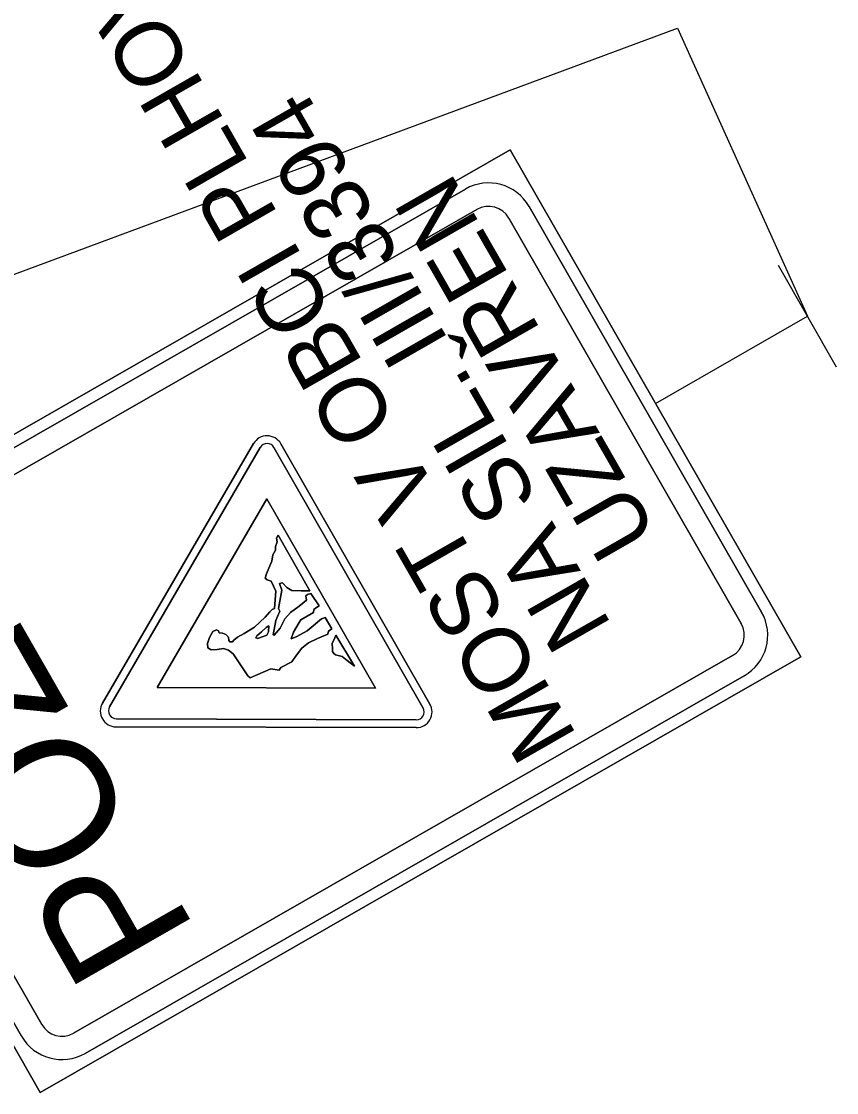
# Model space of a CAD drawing. Extents: x -688893 to -679983, y -1088371 to -1075771.
# Drawn here: x -682889 to -682470, y -1076904 to -1076354 of the extents above; entities that cross this region are included whole.
import ezdxf

# ---------------------------------------------------------------- set-up
doc = ezdxf.new("R2010")
doc.units = 0
for name, color, linetype in [('SDZ', 7, 'Continuous'), ('SDZ plochy', 7, 'Continuous'), ('SDZ symbol', 7, 'Continuous')]:
    doc.layers.add(name, color=color, linetype=linetype)

msp = doc.modelspace()

# ---------------------------------------------------------------- linework, layer by layer
at = {"layer": 'SDZ'}
for p, q in [((-683028.12, -1076644.18), (-682637.66, -1076420.48)), ((-682637.66, -1076420.48), (-682488.53, -1076680.79)), ((-682999.11, -1076634.47), (-682660.71, -1076440.6)), ((-682993.14, -1076644.89), (-682654.75, -1076451.01)), ((-682627.96, -1076449.49), (-682508.65, -1076657.74)), ((-682638.37, -1076455.46), (-682519.06, -1076663.7)), ((-682470.09, -1076531.92), (-682499.92, -1076479.86)), ((-682563.1, -1076550.63), (-682485, -1076505.89)), ((-682847.11, -1076704.5), (-682769.5, -1076571.27)), ((-682766.04, -1076573.25), (-682843.41, -1076706.42)), ((-682682.38, -1076707.05), (-682759.02, -1076573.27)), ((-682678.9, -1076704.98), (-682755.48, -1076571.32)), ((-682762.64, -1076599.54), (-682818.92, -1076696.43)), ((-682706.87, -1076696.89), (-682762.64, -1076599.54)), ((-682756.77, -1076618.35), (-682757.77, -1076619.86)), ((-682740.64, -1076646.92), (-682756.77, -1076618.35)), ((-682758.17, -1076624.05), (-682758.24, -1076625.96)), ((-682757.39, -1076621.74), (-682758.17, -1076624.05)), ((-682757.77, -1076619.86), (-682757.39, -1076621.74)), ((-682759.65, -1076628.4), (-682760.09, -1076631.69)), ((-682758.24, -1076625.96), (-682759.65, -1076628.4)), ((-682761.62, -1076635.13), (-682762.9, -1076638.2)), ((-682760.09, -1076631.69), (-682761.62, -1076635.13)), ((-682762.9, -1076638.2), (-682763.5, -1076640.41)), ((-682763.5, -1076640.41), (-682762.54, -1076641.26)), ((-682878.99, -1076904.49), (-683028.12, -1076644.18)), ((-682762.54, -1076641.26), (-682760.51, -1076641.97)), ((-682760.51, -1076641.97), (-682758.04, -1076647.09)), ((-682756.09, -1076643.17), (-682754.66, -1076642.81)), ((-682754.9, -1076646.45), (-682756.09, -1076643.17)), ((-682754.66, -1076642.81), (-682752.34, -1076645.22)), ((-682752.34, -1076645.22), (-682749.9, -1076646.62)), ((-682758.04, -1076647.09), (-682758.81, -1076655.93)), ((-682756.73, -1076655.9), (-682754.9, -1076646.45)), ((-682749.9, -1076646.62), (-682745.08, -1076646.9)), ((-682742.36, -1076651.64), (-682746, -1076654.66)), ((-682745.08, -1076646.9), (-682740.64, -1076646.92)), ((-682741.71, -1076648.7), (-682742.67, -1076649.48)), ((-682742.67, -1076649.48), (-682742.36, -1076651.64)), ((-682740.11, -1076648.25), (-682741.71, -1076648.7)), ((-682735.75, -1076654.62), (-682740.11, -1076648.25)), ((-682759.97, -1076656.36), (-682761.07, -1076657.69)), ((-682758.81, -1076655.93), (-682759.97, -1076656.36)), ((-682755.92, -1076657.31), (-682756.73, -1076655.9)), ((-682746, -1076654.66), (-682750.44, -1076657.9)), ((-682738.74, -1076657.97), (-682738.46, -1076656.41)), ((-682738.46, -1076656.41), (-682737.69, -1076655.73)), ((-682737.69, -1076655.73), (-682735.75, -1076654.62)), ((-682878.28, -1076869.51), (-682997.59, -1076661.26)), ((-682763.45, -1076660.45), (-682768.97, -1076665.48)), ((-682761.07, -1076657.69), (-682763.45, -1076660.45)), ((-682759.5, -1076669.39), (-682758.1, -1076662.06)), ((-682758.1, -1076662.06), (-682757.12, -1076660.1)), ((-682757.12, -1076660.1), (-682755.92, -1076657.31)), ((-682753.43, -1076661.25), (-682755.78, -1076666.1)), ((-682750.44, -1076657.9), (-682753.43, -1076661.25)), ((-682746.07, -1076663.1), (-682745.24, -1076661.69)), ((-682745.24, -1076661.69), (-682738.74, -1076657.97)), ((-682734.57, -1076661.18), (-682742.02, -1076667.31)), ((-682732.78, -1076660.62), (-682734.57, -1076661.18)), ((-682729.29, -1076666.32), (-682732.78, -1076660.62)), ((-682790.34, -1076667.69), (-682792.07, -1076670.78)), ((-682788.49, -1076666.86), (-682790.34, -1076667.69)), ((-682787.46, -1076667.44), (-682788.49, -1076666.86)), ((-682787.13, -1076668.42), (-682787.46, -1076667.44)), ((-682768.97, -1076665.48), (-682774.32, -1076668.78)), ((-682765.48, -1076667.92), (-682767.81, -1076669.95)), ((-682763.07, -1076665.6), (-682765.48, -1076667.92)), ((-682761.66, -1076664.8), (-682763.07, -1076665.6)), ((-682762.66, -1076669.57), (-682761.76, -1076667.89)), ((-682761.76, -1076667.89), (-682761.66, -1076664.8)), ((-682755.78, -1076666.1), (-682758.95, -1076669.54)), ((-682750.13, -1076671.49), (-682749.05, -1076668.07)), ((-682749.05, -1076668.07), (-682746.07, -1076663.1)), ((-682742.02, -1076667.31), (-682747.29, -1076670.33)), ((-682731.39, -1076669.16), (-682730.94, -1076667.5)), ((-682730.94, -1076667.5), (-682729.29, -1076666.32)), ((-682792.07, -1076670.78), (-682793.07, -1076673.93)), ((-682785.4, -1076668.59), (-682787.13, -1076668.42)), ((-682783.64, -1076669.22), (-682785.4, -1076668.59)), ((-682782.38, -1076670.6), (-682783.64, -1076669.22)), ((-682782.1, -1076672.31), (-682782.38, -1076670.6)), ((-682781.7, -1076673.01), (-682782.1, -1076672.31)), ((-682780.24, -1076673.11), (-682781.7, -1076673.01)), ((-682779.56, -1076672.25), (-682780.24, -1076673.11)), ((-682777.66, -1076670.69), (-682779.56, -1076672.25)), ((-682774.32, -1076668.78), (-682777.66, -1076670.69)), ((-682767.81, -1076669.95), (-682768.39, -1076670.98)), ((-682768.39, -1076670.98), (-682767.46, -1076671.38)), ((-682767.46, -1076671.38), (-682763.99, -1076670.1)), ((-682763.99, -1076670.1), (-682762.66, -1076669.57)), ((-682758.95, -1076669.54), (-682759.5, -1076669.39)), ((-682747.29, -1076670.33), (-682750.13, -1076671.49)), ((-682744.77, -1076676.36), (-682741.21, -1076673.62)), ((-682741.21, -1076673.62), (-682736.72, -1076671.27)), ((-682736.72, -1076671.27), (-682731.39, -1076669.16)), ((-682728, -1076671.42), (-682729.05, -1076673.65)), ((-682727.2, -1076669.56), (-682728, -1076671.42)), ((-682717.59, -1076685.52), (-682727.2, -1076669.56)), ((-682793.07, -1076673.93), (-682792.95, -1076676.19)), ((-682792.95, -1076676.19), (-682791.26, -1076677.09)), ((-682791.26, -1076677.09), (-682788.1, -1076676.91)), ((-682788.1, -1076676.91), (-682784.86, -1076676.45)), ((-682784.86, -1076676.45), (-682782.27, -1076677.3)), ((-682782.27, -1076677.3), (-682779.98, -1076679.26)), ((-682747.98, -1076680.53), (-682744.77, -1076676.36)), ((-682729.05, -1076673.65), (-682728.87, -1076676.82)), ((-682728.87, -1076676.82), (-682728.9, -1076678)), ((-682728.9, -1076678), (-682728.29, -1076679.05)), ((-682728.29, -1076679.05), (-682727.44, -1076679.73)), ((-682488.53, -1076680.79), (-682878.99, -1076904.49)), ((-682523.51, -1076680.08), (-682861.9, -1076873.96)), ((-682779.98, -1076679.26), (-682772.36, -1076690.53)), ((-682755.46, -1076686.22), (-682749.91, -1076683.27)), ((-682749.91, -1076683.27), (-682747.98, -1076680.53)), ((-682727.44, -1076679.73), (-682723.95, -1076680.53)), ((-682723.95, -1076680.53), (-682721.38, -1076682.56)), ((-682721.38, -1076682.56), (-682717.59, -1076685.52)), ((-682771.3, -1076691.56), (-682760.68, -1076686.87)), ((-682760.68, -1076686.87), (-682756.29, -1076687.62)), ((-682756.29, -1076687.62), (-682755.46, -1076686.22)), ((-682517.54, -1076690.49), (-682855.94, -1076884.37)), ((-682772.36, -1076690.53), (-682771.3, -1076691.56)), ((-682818.92, -1076696.43), (-682706.87, -1076696.89)), ((-682847.04, -1076704.38), (-682847.04, -1076704.38)), ((-682685.95, -1076717.11), (-682840.14, -1076716.68)), ((-682840.05, -1076712.51), (-682840.05, -1076712.51)), ((-682839.92, -1076712.51), (-682685.91, -1076713.11))]:
    msp.add_line(p, q, dxfattribs=at)
msp.add_lwpolyline([(-683189.1, -1076594.26), (-682551.71, -1076357.85), (-682485, -1076505.89)], dxfattribs=at)
for centre, radius, start, end in [((-682648.78, -1076461.42), 24, 29.8094, 119.8094), ((-682648.78, -1076461.42), 12, 29.8094, 119.8094), ((-682762.5, -1076575.34), 8.1, 29.8094, 149.7784), ((-682762.54, -1076575.29), 4.05, 29.8094, 149.8437), ((-682529.47, -1076669.67), 24, 299.8094, 29.8094), ((-682529.47, -1076669.67), 12, 299.8094, 29.8094), ((-682840.11, -1076708.58), 8.1, 149.7784, 269.8403), ((-682839.91, -1076708.46), 4.05, 149.8437, 269.7751), ((-682685.93, -1076709.01), 8.1, 269.8403, 29.8094), ((-682685.89, -1076709.06), 4.05, 269.7751, 29.8094), ((-682867.87, -1076863.54), 12, 209.8094, 299.8094), ((-682867.87, -1076863.54), 24, 209.8094, 299.8094)]:
    msp.add_arc(centre, radius, start, end, dxfattribs=at)
at = {"layer": 'SDZ plochy'}
for p, q in [((-682637.66, -1076420.48), (-683028.12, -1076644.18)), ((-682488.53, -1076680.79), (-682637.66, -1076420.48)), ((-682660.71, -1076440.6), (-682999.11, -1076634.47)), ((-682999.11, -1076634.47), (-682660.71, -1076440.6)), ((-682993.14, -1076644.89), (-682654.75, -1076451.01)), ((-682654.75, -1076451.01), (-682993.14, -1076644.89)), ((-682508.65, -1076657.74), (-682627.96, -1076449.49)), ((-682627.96, -1076449.49), (-682508.65, -1076657.74)), ((-682638.37, -1076455.46), (-682519.06, -1076663.7)), ((-682519.06, -1076663.7), (-682638.37, -1076455.46)), ((-682847.11, -1076704.5), (-682769.5, -1076571.27)), ((-682769.5, -1076571.27), (-682847.11, -1076704.5)), ((-682766.04, -1076573.25), (-682843.41, -1076706.42)), ((-682843.41, -1076706.42), (-682766.04, -1076573.25)), ((-682682.38, -1076707.05), (-682759.02, -1076573.27)), ((-682759.02, -1076573.27), (-682682.38, -1076707.05)), ((-682755.48, -1076571.32), (-682678.9, -1076704.98)), ((-682678.9, -1076704.98), (-682755.48, -1076571.32)), ((-682818.92, -1076696.43), (-682762.64, -1076599.54)), ((-682762.64, -1076599.54), (-682818.92, -1076696.43)), ((-682762.64, -1076599.54), (-682706.87, -1076696.89)), ((-682706.87, -1076696.89), (-682762.64, -1076599.54)), ((-682756.77, -1076618.35), (-682757.77, -1076619.86)), ((-682757.77, -1076619.86), (-682756.77, -1076618.35)), ((-682740.64, -1076646.92), (-682756.77, -1076618.35)), ((-682756.77, -1076618.35), (-682740.64, -1076646.92)), ((-682758.17, -1076624.05), (-682758.24, -1076625.96)), ((-682758.24, -1076625.96), (-682758.17, -1076624.05)), ((-682757.39, -1076621.74), (-682758.17, -1076624.05)), ((-682758.17, -1076624.05), (-682757.39, -1076621.74)), ((-682757.77, -1076619.86), (-682757.39, -1076621.74)), ((-682757.39, -1076621.74), (-682757.77, -1076619.86)), ((-682759.65, -1076628.4), (-682760.09, -1076631.69)), ((-682760.09, -1076631.69), (-682759.65, -1076628.4)), ((-682758.24, -1076625.96), (-682759.65, -1076628.4)), ((-682759.65, -1076628.4), (-682758.24, -1076625.96)), ((-682761.62, -1076635.13), (-682762.9, -1076638.2)), ((-682762.9, -1076638.2), (-682761.62, -1076635.13)), ((-682760.09, -1076631.69), (-682761.62, -1076635.13)), ((-682761.62, -1076635.13), (-682760.09, -1076631.69)), ((-682762.9, -1076638.2), (-682763.5, -1076640.41)), ((-682763.5, -1076640.41), (-682762.9, -1076638.2)), ((-682763.5, -1076640.41), (-682762.54, -1076641.26)), ((-682762.54, -1076641.26), (-682763.5, -1076640.41)), ((-683028.12, -1076644.18), (-682878.99, -1076904.49)), ((-682762.54, -1076641.26), (-682760.51, -1076641.97)), ((-682760.51, -1076641.97), (-682762.54, -1076641.26)), ((-682760.51, -1076641.97), (-682758.04, -1076647.09)), ((-682758.04, -1076647.09), (-682760.51, -1076641.97)), ((-682756.09, -1076643.17), (-682754.66, -1076642.81)), ((-682754.66, -1076642.81), (-682756.09, -1076643.17)), ((-682754.9, -1076646.45), (-682756.09, -1076643.17)), ((-682756.09, -1076643.17), (-682754.9, -1076646.45)), ((-682754.66, -1076642.81), (-682752.34, -1076645.22)), ((-682752.34, -1076645.22), (-682754.66, -1076642.81)), ((-682752.34, -1076645.22), (-682749.9, -1076646.62)), ((-682749.9, -1076646.62), (-682752.34, -1076645.22)), ((-682758.04, -1076647.09), (-682758.81, -1076655.93)), ((-682758.81, -1076655.93), (-682758.04, -1076647.09)), ((-682756.73, -1076655.9), (-682754.9, -1076646.45)), ((-682754.9, -1076646.45), (-682756.73, -1076655.9)), ((-682749.9, -1076646.62), (-682745.08, -1076646.9)), ((-682745.08, -1076646.9), (-682749.9, -1076646.62)), ((-682742.36, -1076651.64), (-682746, -1076654.66)), ((-682746, -1076654.66), (-682742.36, -1076651.64)), ((-682745.08, -1076646.9), (-682740.64, -1076646.92)), ((-682740.64, -1076646.92), (-682745.08, -1076646.9)), ((-682741.71, -1076648.7), (-682742.67, -1076649.48)), ((-682742.67, -1076649.48), (-682741.71, -1076648.7)), ((-682742.67, -1076649.48), (-682742.36, -1076651.64)), ((-682742.36, -1076651.64), (-682742.67, -1076649.48)), ((-682740.11, -1076648.25), (-682741.71, -1076648.7)), ((-682741.71, -1076648.7), (-682740.11, -1076648.25)), ((-682735.75, -1076654.62), (-682740.11, -1076648.25)), ((-682740.11, -1076648.25), (-682735.75, -1076654.62)), ((-682759.97, -1076656.36), (-682761.07, -1076657.69)), ((-682761.07, -1076657.69), (-682759.97, -1076656.36)), ((-682758.81, -1076655.93), (-682759.97, -1076656.36)), ((-682759.97, -1076656.36), (-682758.81, -1076655.93)), ((-682755.92, -1076657.31), (-682756.73, -1076655.9)), ((-682756.73, -1076655.9), (-682755.92, -1076657.31)), ((-682746, -1076654.66), (-682750.44, -1076657.9)), ((-682750.44, -1076657.9), (-682746, -1076654.66)), ((-682738.74, -1076657.97), (-682738.46, -1076656.41)), ((-682738.46, -1076656.41), (-682738.74, -1076657.97)), ((-682738.46, -1076656.41), (-682737.69, -1076655.73)), ((-682737.69, -1076655.73), (-682738.46, -1076656.41)), ((-682737.69, -1076655.73), (-682735.75, -1076654.62)), ((-682735.75, -1076654.62), (-682737.69, -1076655.73)), ((-682878.28, -1076869.51), (-682997.59, -1076661.26)), ((-682997.59, -1076661.26), (-682878.28, -1076869.51)), ((-682763.45, -1076660.45), (-682768.97, -1076665.48)), ((-682768.97, -1076665.48), (-682763.45, -1076660.45)), ((-682761.07, -1076657.69), (-682763.45, -1076660.45)), ((-682763.45, -1076660.45), (-682761.07, -1076657.69)), ((-682759.5, -1076669.39), (-682758.1, -1076662.06)), ((-682758.1, -1076662.06), (-682759.5, -1076669.39)), ((-682758.1, -1076662.06), (-682757.12, -1076660.1)), ((-682757.12, -1076660.1), (-682758.1, -1076662.06)), ((-682757.12, -1076660.1), (-682755.92, -1076657.31)), ((-682755.92, -1076657.31), (-682757.12, -1076660.1)), ((-682753.43, -1076661.25), (-682755.78, -1076666.1)), ((-682755.78, -1076666.1), (-682753.43, -1076661.25)), ((-682750.44, -1076657.9), (-682753.43, -1076661.25)), ((-682753.43, -1076661.25), (-682750.44, -1076657.9)), ((-682746.07, -1076663.1), (-682745.24, -1076661.69)), ((-682745.24, -1076661.69), (-682746.07, -1076663.1)), ((-682745.24, -1076661.69), (-682738.74, -1076657.97)), ((-682738.74, -1076657.97), (-682745.24, -1076661.69)), ((-682734.57, -1076661.18), (-682742.02, -1076667.31)), ((-682742.02, -1076667.31), (-682734.57, -1076661.18)), ((-682732.78, -1076660.62), (-682734.57, -1076661.18)), ((-682734.57, -1076661.18), (-682732.78, -1076660.62)), ((-682729.29, -1076666.32), (-682732.78, -1076660.62)), ((-682732.78, -1076660.62), (-682729.29, -1076666.32)), ((-683008, -1076667.23), (-682888.69, -1076875.47)), ((-682888.69, -1076875.47), (-683008, -1076667.23)), ((-682790.34, -1076667.69), (-682792.07, -1076670.78)), ((-682792.07, -1076670.78), (-682790.34, -1076667.69)), ((-682788.49, -1076666.86), (-682790.34, -1076667.69)), ((-682790.34, -1076667.69), (-682788.49, -1076666.86)), ((-682787.46, -1076667.44), (-682788.49, -1076666.86)), ((-682788.49, -1076666.86), (-682787.46, -1076667.44)), ((-682787.13, -1076668.42), (-682787.46, -1076667.44)), ((-682787.46, -1076667.44), (-682787.13, -1076668.42)), ((-682768.97, -1076665.48), (-682774.32, -1076668.78)), ((-682774.32, -1076668.78), (-682768.97, -1076665.48)), ((-682767.81, -1076669.95), (-682765.48, -1076667.92)), ((-682765.48, -1076667.92), (-682767.81, -1076669.95)), ((-682765.48, -1076667.92), (-682763.07, -1076665.6)), ((-682763.07, -1076665.6), (-682765.48, -1076667.92)), ((-682763.07, -1076665.6), (-682761.66, -1076664.8)), ((-682761.66, -1076664.8), (-682763.07, -1076665.6)), ((-682761.76, -1076667.89), (-682762.66, -1076669.57)), ((-682762.66, -1076669.57), (-682761.76, -1076667.89)), ((-682761.66, -1076664.8), (-682761.76, -1076667.89)), ((-682761.76, -1076667.89), (-682761.66, -1076664.8)), ((-682755.78, -1076666.1), (-682758.95, -1076669.54)), ((-682758.95, -1076669.54), (-682755.78, -1076666.1)), ((-682750.13, -1076671.49), (-682749.05, -1076668.07)), ((-682749.05, -1076668.07), (-682750.13, -1076671.49)), ((-682749.05, -1076668.07), (-682746.07, -1076663.1)), ((-682746.07, -1076663.1), (-682749.05, -1076668.07)), ((-682742.02, -1076667.31), (-682747.29, -1076670.33)), ((-682747.29, -1076670.33), (-682742.02, -1076667.31)), ((-682731.39, -1076669.16), (-682730.94, -1076667.5)), ((-682730.94, -1076667.5), (-682731.39, -1076669.16)), ((-682730.94, -1076667.5), (-682729.29, -1076666.32)), ((-682729.29, -1076666.32), (-682730.94, -1076667.5)), ((-682792.07, -1076670.78), (-682793.07, -1076673.93)), ((-682793.07, -1076673.93), (-682792.07, -1076670.78)), ((-682785.4, -1076668.59), (-682787.13, -1076668.42)), ((-682787.13, -1076668.42), (-682785.4, -1076668.59)), ((-682783.64, -1076669.22), (-682785.4, -1076668.59)), ((-682785.4, -1076668.59), (-682783.64, -1076669.22)), ((-682782.38, -1076670.6), (-682783.64, -1076669.22)), ((-682783.64, -1076669.22), (-682782.38, -1076670.6)), ((-682782.1, -1076672.31), (-682782.38, -1076670.6)), ((-682782.38, -1076670.6), (-682782.1, -1076672.31)), ((-682781.7, -1076673.01), (-682782.1, -1076672.31)), ((-682782.1, -1076672.31), (-682781.7, -1076673.01)), ((-682780.24, -1076673.11), (-682781.7, -1076673.01)), ((-682781.7, -1076673.01), (-682780.24, -1076673.11)), ((-682779.56, -1076672.25), (-682780.24, -1076673.11)), ((-682780.24, -1076673.11), (-682779.56, -1076672.25)), ((-682777.66, -1076670.69), (-682779.56, -1076672.25)), ((-682779.56, -1076672.25), (-682777.66, -1076670.69)), ((-682774.32, -1076668.78), (-682777.66, -1076670.69)), ((-682777.66, -1076670.69), (-682774.32, -1076668.78)), ((-682768.39, -1076670.98), (-682767.81, -1076669.95)), ((-682767.81, -1076669.95), (-682768.39, -1076670.98)), ((-682767.46, -1076671.38), (-682768.39, -1076670.98)), ((-682768.39, -1076670.98), (-682767.46, -1076671.38)), ((-682763.99, -1076670.1), (-682767.46, -1076671.38)), ((-682767.46, -1076671.38), (-682763.99, -1076670.1)), ((-682762.66, -1076669.57), (-682763.99, -1076670.1)), ((-682763.99, -1076670.1), (-682762.66, -1076669.57)), ((-682758.95, -1076669.54), (-682759.5, -1076669.39)), ((-682759.5, -1076669.39), (-682758.95, -1076669.54)), ((-682747.29, -1076670.33), (-682750.13, -1076671.49)), ((-682750.13, -1076671.49), (-682747.29, -1076670.33)), ((-682744.77, -1076676.36), (-682741.21, -1076673.62)), ((-682741.21, -1076673.62), (-682744.77, -1076676.36)), ((-682741.21, -1076673.62), (-682736.72, -1076671.27)), ((-682736.72, -1076671.27), (-682741.21, -1076673.62)), ((-682736.72, -1076671.27), (-682731.39, -1076669.16)), ((-682731.39, -1076669.16), (-682736.72, -1076671.27)), ((-682728, -1076671.42), (-682729.05, -1076673.65)), ((-682729.05, -1076673.65), (-682728, -1076671.42)), ((-682727.2, -1076669.56), (-682728, -1076671.42)), ((-682728, -1076671.42), (-682727.2, -1076669.56)), ((-682717.59, -1076685.52), (-682727.2, -1076669.56)), ((-682727.2, -1076669.56), (-682717.59, -1076685.52)), ((-682793.07, -1076673.93), (-682792.95, -1076676.19)), ((-682792.95, -1076676.19), (-682793.07, -1076673.93)), ((-682792.95, -1076676.19), (-682791.26, -1076677.09)), ((-682791.26, -1076677.09), (-682792.95, -1076676.19)), ((-682791.26, -1076677.09), (-682788.1, -1076676.91)), ((-682788.1, -1076676.91), (-682791.26, -1076677.09)), ((-682788.1, -1076676.91), (-682784.86, -1076676.45)), ((-682784.86, -1076676.45), (-682788.1, -1076676.91)), ((-682784.86, -1076676.45), (-682782.27, -1076677.3)), ((-682782.27, -1076677.3), (-682784.86, -1076676.45)), ((-682782.27, -1076677.3), (-682779.98, -1076679.26)), ((-682779.98, -1076679.26), (-682782.27, -1076677.3)), ((-682747.98, -1076680.53), (-682744.77, -1076676.36)), ((-682744.77, -1076676.36), (-682747.98, -1076680.53)), ((-682729.05, -1076673.65), (-682728.87, -1076676.82)), ((-682728.87, -1076676.82), (-682729.05, -1076673.65)), ((-682728.87, -1076676.82), (-682728.9, -1076678)), ((-682728.9, -1076678), (-682728.87, -1076676.82)), ((-682728.9, -1076678), (-682728.29, -1076679.05)), ((-682728.29, -1076679.05), (-682728.9, -1076678)), ((-682728.29, -1076679.05), (-682727.44, -1076679.73)), ((-682727.44, -1076679.73), (-682728.29, -1076679.05)), ((-682878.99, -1076904.49), (-682488.53, -1076680.79)), ((-682523.51, -1076680.08), (-682861.9, -1076873.96)), ((-682861.9, -1076873.96), (-682523.51, -1076680.08)), ((-682779.98, -1076679.26), (-682772.36, -1076690.53)), ((-682772.36, -1076690.53), (-682779.98, -1076679.26)), ((-682755.46, -1076686.22), (-682749.91, -1076683.27)), ((-682749.91, -1076683.27), (-682755.46, -1076686.22)), ((-682749.91, -1076683.27), (-682747.98, -1076680.53)), ((-682747.98, -1076680.53), (-682749.91, -1076683.27)), ((-682727.44, -1076679.73), (-682723.95, -1076680.53)), ((-682723.95, -1076680.53), (-682727.44, -1076679.73)), ((-682723.95, -1076680.53), (-682721.38, -1076682.56)), ((-682721.38, -1076682.56), (-682723.95, -1076680.53)), ((-682721.38, -1076682.56), (-682717.59, -1076685.52)), ((-682717.59, -1076685.52), (-682721.38, -1076682.56)), ((-682771.3, -1076691.56), (-682760.68, -1076686.87)), ((-682760.68, -1076686.87), (-682771.3, -1076691.56)), ((-682760.68, -1076686.87), (-682756.29, -1076687.62)), ((-682756.29, -1076687.62), (-682760.68, -1076686.87)), ((-682756.29, -1076687.62), (-682755.46, -1076686.22)), ((-682755.46, -1076686.22), (-682756.29, -1076687.62)), ((-682855.94, -1076884.37), (-682517.54, -1076690.49)), ((-682517.54, -1076690.49), (-682855.94, -1076884.37)), ((-682772.36, -1076690.53), (-682771.3, -1076691.56)), ((-682771.3, -1076691.56), (-682772.36, -1076690.53)), ((-682706.87, -1076696.89), (-682818.92, -1076696.43)), ((-682818.92, -1076696.43), (-682706.87, -1076696.89)), ((-682685.95, -1076717.11), (-682840.14, -1076716.68)), ((-682840.14, -1076716.68), (-682685.95, -1076717.11)), ((-682839.92, -1076712.51), (-682685.91, -1076713.11)), ((-682685.91, -1076713.11), (-682839.92, -1076712.51))]:
    msp.add_line(p, q, dxfattribs=at)
for centre, radius, start, end in [((-682648.78, -1076461.42), 24, 29.8094, 119.8094), ((-682648.78, -1076461.42), 24, 29.8094, 119.8094), ((-682648.78, -1076461.42), 12, 29.8094, 119.8094), ((-682648.78, -1076461.42), 12, 29.8094, 119.8094), ((-682762.5, -1076575.34), 8.1, 29.8094, 149.7784), ((-682762.5, -1076575.34), 8.1, 29.8094, 149.7784), ((-682762.54, -1076575.29), 4.05, 29.8094, 149.8437), ((-682762.54, -1076575.29), 4.05, 29.8094, 149.8437), ((-682529.47, -1076669.67), 24, 299.8094, 29.8094), ((-682529.47, -1076669.67), 24, 299.8094, 29.8094), ((-682529.47, -1076669.67), 12, 299.8094, 29.8094), ((-682529.47, -1076669.67), 12, 299.8094, 29.8094), ((-682840.11, -1076708.58), 8.1, 149.7784, 269.8403), ((-682840.11, -1076708.58), 8.1, 149.7784, 269.8403), ((-682839.91, -1076708.46), 4.05, 149.8437, 269.7751), ((-682839.91, -1076708.46), 4.05, 149.8437, 269.7751), ((-682685.93, -1076709.01), 8.1, 269.8403, 29.8094), ((-682685.93, -1076709.01), 8.1, 269.8403, 29.8094), ((-682685.89, -1076709.06), 4.05, 269.7751, 29.8094), ((-682685.89, -1076709.06), 4.05, 269.7751, 29.8094), ((-682867.87, -1076863.54), 12, 209.8094, 299.8094), ((-682867.87, -1076863.54), 12, 209.8094, 299.8094), ((-682867.87, -1076863.54), 24, 209.8094, 299.8094), ((-682867.87, -1076863.54), 24, 209.8094, 299.8094)]:
    msp.add_arc(centre, radius, start, end, dxfattribs=at)

# ---------------------------------------------------------------- texts
at = {"layer": 'SDZ symbol'}
for s, height, p in [('MOST V OBCI PLHOV', 33.75, (-682603, -1076721.64)), ('NA SIL. III/3394', 33.75, (-682585.15, -1076664.93)), ('UZAVŘEN', 33.75, (-682561.7, -1076618)), ('POZOR', 67.5, (-682798.48, -1076821.71))]:
    msp.add_text(s, height=height, rotation=119.8094, dxfattribs=at).set_placement(p)

doc.saveas('drawing.dxf')
